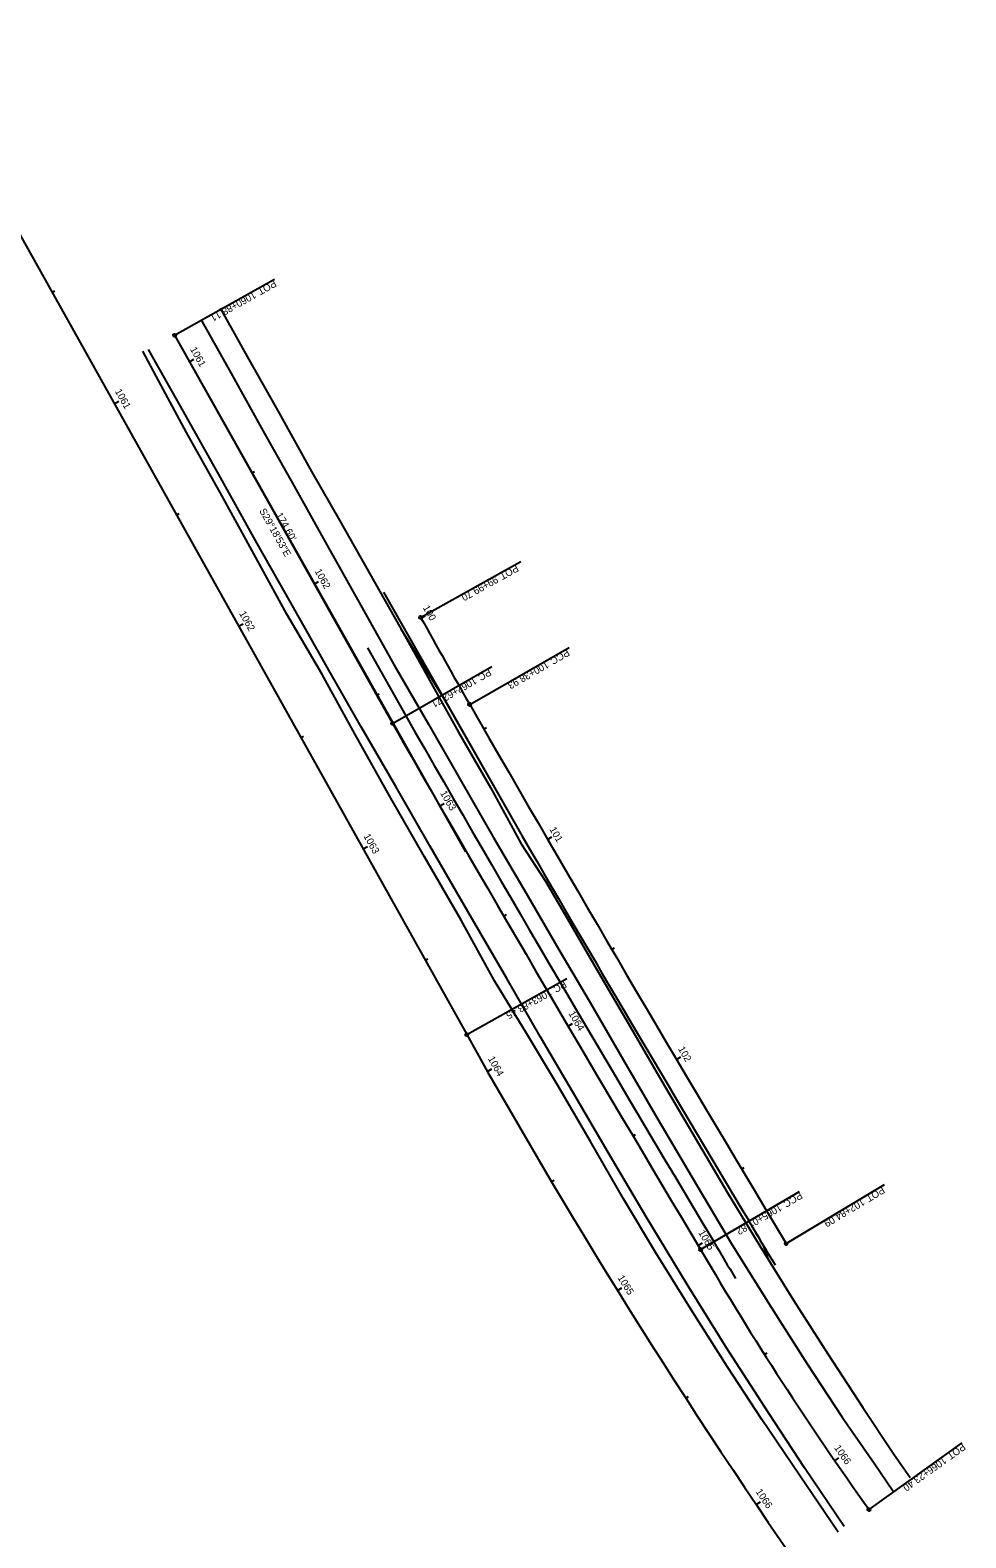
# Model space of a CAD drawing. Extents: x 1948127 to 1949841, y 151410 to 153356.
# Drawn here: x 1948495 to 1948862, y 152173 to 152764 of the extents above; entities that cross this region are included whole.
import ezdxf

# ---------------------------------------------------------------- set-up
doc = ezdxf.new("R2010")
doc.units = 0
for name, color, linetype in [('BR_P_Brg_Pad_Hidden', 7, 'Continuous'), ('BR_P_Gen_Hatch', 7, 'Continuous'), ('BR_P_Slab_Stl_Det', 7, 'Continuous'), ('BR_P_Slab_Stl_Det_Hidden', 7, 'Continuous'), ('BR_P_Sub_Deep_Centerline', 7, 'Continuous'), ('BR_P_Sub_Deep_Hidden', 7, 'Continuous'), ('CM_Corridor_Top_Mesh', 7, 'Continuous'), ('DR_P_Ditch', 7, 'Continuous'), ('DR_X_Storm_Sewer', 7, 'Continuous'), ('GE_X_Alignment_100_Stations', 7, 'Continuous'), ('MD_P_Surface_Chemically_Stabilized_Subgrade', 7, 'Continuous'), ('SC_Scratch1', 7, 'Continuous'), ('SC_Scratch11', 7, 'Continuous'), ('TX_P_1', 7, 'Continuous')]:
    doc.layers.add(name, color=color, linetype=linetype)

msp = doc.modelspace()

# ---------------------------------------------------------------- linework, layer by layer
at = {"layer": 'BR_P_Gen_Hatch'}
msp.add_line((1948551.61, 152644.81), (1948665.76, 152442.26), dxfattribs=at)
at = {"layer": 'BR_P_Slab_Stl_Det'}
for points in [[(1948562.39, 152650.4), (1948573.72, 152630.13), (1948586.43, 152607.26), (1948598.51, 152585.61), (1948611.32, 152562.7), (1948624.06, 152540.02), (1948637.72, 152515.73), (1948651.27, 152492.37), (1948663.63, 152470.62), (1948676.95, 152447.56), (1948689.61, 152426.05), (1948702.36, 152403.96), (1948714.65, 152383.15), (1948727.73, 152360.55), (1948741.26, 152337.36), (1948754.52, 152314.84), (1948770.02, 152288.76), (1948784.79, 152265.13), (1948799.87, 152241.41), (1948813.52, 152220.53), (1948826.05, 152202.51), (1948833.51, 152191.53)], [(1948814.36, 152177.61), (1948798.77, 152200.66), (1948784.61, 152222.18), (1948767.92, 152248.18), (1948752.79, 152272.55), (1948736.61, 152299.16), (1948721.69, 152324.29), (1948707.75, 152348.29), (1948695.05, 152369.83), (1948682, 152392.51), (1948666.63, 152418.86), (1948651.77, 152444.62), (1948638.4, 152467.86), (1948624.88, 152491.29), (1948612.64, 152512.63), (1948597.75, 152538.95), (1948584.01, 152563.11), (1948569.69, 152589.07), (1948555.07, 152614.97), (1948541.37, 152639.28)]]:
    msp.add_lwpolyline(points, dxfattribs=at)
at = {"layer": 'BR_P_Slab_Stl_Det_Hidden'}
for p, q in [((1948557.46, 152634.46), (1948559.2, 152635.44)), ((1948581.94, 152590.87), (1948582.98, 152591.45)), ((1948606.42, 152547.27), (1948608.16, 152548.25)), ((1948648.32, 152533.93), (1948650.07, 152534.9)), ((1948630.9, 152503.67), (1948631.95, 152504.26)), ((1948672.96, 152490.42), (1948674, 152491.02)), ((1948655.71, 152460.26), (1948657.44, 152461.26)), ((1948697.98, 152447.13), (1948699.71, 152448.13)), ((1948680.79, 152417.01), (1948681.83, 152417.61)), ((1948723.17, 152403.94), (1948724.21, 152404.55)), ((1948706.04, 152373.85), (1948707.77, 152374.87)), ((1948748.54, 152360.85), (1948750.26, 152361.87)), ((1948731.47, 152330.8), (1948732.5, 152331.41)), ((1948774.07, 152317.86), (1948775.1, 152318.48)), ((1948757.07, 152287.85), (1948758.79, 152288.88)), ((1948783.08, 152245.15), (1948784.09, 152245.79)), ((1948810.66, 152203.45), (1948812.31, 152204.59))]:
    msp.add_line(p, q, dxfattribs=at)
at = {"layer": 'BR_P_Sub_Deep_Centerline'}
for p, q in [((1948503.58, 152661.62), (1948504.63, 152662.21)), ((1948527.97, 152617.98), (1948529.72, 152618.95)), ((1948552.37, 152574.33), (1948553.42, 152574.92)), ((1948576.76, 152530.69), (1948578.51, 152531.67)), ((1948601.16, 152487.04), (1948602.21, 152487.63)), ((1948625.56, 152443.4), (1948627.3, 152444.38)), ((1948649.95, 152399.76), (1948651, 152400.34)), ((1948674.39, 152356.14), (1948676.13, 152357.12)), ((1948699.5, 152312.9), (1948700.53, 152313.51)), ((1948725.45, 152270.16), (1948727.14, 152271.21)), ((1948752.23, 152227.94), (1948753.23, 152228.59)), ((1948779.83, 152186.25), (1948781.49, 152187.37))]:
    msp.add_line(p, q, dxfattribs=at)
at = {"layer": 'BR_P_Sub_Deep_Hidden'}
msp.add_line((1948666.27, 152370.56), (1948705.55, 152392.51), dxfattribs=at)
msp.add_circle((1948666.27, 152370.56), 0.6, dxfattribs=at)
at = {"layer": 'CM_Corridor_Top_Mesh'}
for points in [[(1948562.39, 152650.4), (1948573.72, 152630.13), (1948586.43, 152607.26), (1948598.51, 152585.61), (1948611.32, 152562.7), (1948624.06, 152540.02), (1948637.72, 152515.73), (1948651.27, 152492.37), (1948663.63, 152470.62), (1948676.95, 152447.56), (1948689.61, 152426.05), (1948702.36, 152403.96), (1948714.65, 152383.15), (1948727.73, 152360.55), (1948741.26, 152337.36), (1948754.52, 152314.84), (1948770.02, 152288.76), (1948784.79, 152265.13), (1948799.87, 152241.41), (1948813.52, 152220.53), (1948826.05, 152202.51), (1948833.51, 152191.53)], [(1948814.36, 152177.61), (1948798.77, 152200.66), (1948784.61, 152222.18), (1948767.92, 152248.18), (1948752.79, 152272.55), (1948736.61, 152299.16), (1948721.69, 152324.29), (1948707.75, 152348.29), (1948695.05, 152369.83), (1948682, 152392.51), (1948666.63, 152418.86), (1948651.77, 152444.62), (1948638.4, 152467.86), (1948624.88, 152491.29), (1948612.64, 152512.63), (1948597.75, 152538.95), (1948584.01, 152563.11), (1948569.69, 152589.07), (1948555.07, 152614.97), (1948541.37, 152639.28)]]:
    msp.add_lwpolyline(points, dxfattribs=at)
at = {"layer": 'DR_P_Ditch'}
for p, q in [((1948633.62, 152544.11), (1948685.2, 152453.22)), ((1948640.35, 152529.74), (1948656.68, 152503.46)), ((1948656.68, 152503.46), (1948685.2, 152453.22)), ((1948656.68, 152503.46), (1948685.2, 152453.22)), ((1948776.88, 152297.6), (1948776.94, 152297.49)), ((1948776.88, 152297.6), (1948776.94, 152297.49)), ((1948776.88, 152297.6), (1948776.94, 152297.49)), ((1948776.94, 152297.49), (1948777, 152297.39)), ((1948776.94, 152297.49), (1948777, 152297.39)), ((1948776.94, 152297.49), (1948777, 152297.39)), ((1948782.53, 152288.02), (1948784.44, 152282.6))]:
    msp.add_line(p, q, dxfattribs=at)
for centre, radius, start, end in [((1959364.39, 158640.02), 12341.86, 210.085088, 210.92362), ((1959364.39, 158640.02), 12341.86, 210.085088, 210.92362), ((1959364.39, 158640.02), 12341.86, 210.085088, 210.92362), ((1949896.82, 152951.97), 1297.1, 210.30805, 211.19069), ((1949896.82, 152951.97), 1297.1, 210.30805, 210.78706), ((1949896.82, 152951.97), 1297.1, 210.30805, 210.78706)]:
    msp.add_arc(centre, radius, start, end, dxfattribs=at)
at = {"layer": 'DR_X_Storm_Sewer'}
for p, q in [((1948551.64, 152644.83), (1948590.87, 152666.86)), ((1948648.18, 152534.19), (1948687.49, 152556.08)), ((1948667.44, 152500.02), (1948706.46, 152522.43)), ((1948637.12, 152492.59), (1948676.17, 152514.96)), ((1948791.58, 152288.61), (1948830.16, 152311.76)), ((1948758.01, 152286.29), (1948796.86, 152309)), ((1948824.11, 152184.3), (1948860.7, 152210.49))]:
    msp.add_line(p, q, dxfattribs=at)
for centre in [(1948551.64, 152644.83), (1948648.18, 152534.19), (1948667.44, 152500.02), (1948637.12, 152492.59), (1948758.01, 152286.29), (1948791.58, 152288.61), (1948824.11, 152184.3)]:
    msp.add_circle(centre, 0.6, dxfattribs=at)
at = {"layer": 'GE_X_Alignment_100_Stations'}
for points in [[(1948569.54, 152655.45), (1948580.78, 152635.37), (1948592.65, 152614.23), (1948605.3, 152591.41), (1948616.41, 152572.05), (1948628.19, 152551.33), (1948639.95, 152530.43), (1948651.66, 152509.56), (1948663.01, 152489.14), (1948675.59, 152467.47), (1948687.61, 152445.42), (1948697.12, 152430.76), (1948705.79, 152416), (1948717.95, 152394.92), (1948730.53, 152373.49), (1948742.79, 152352.28), (1948755.91, 152330.05), (1948768.46, 152308.76), (1948781.28, 152287.71), (1948794.43, 152266.42), (1948807.98, 152245.32), (1948821.66, 152224.39), (1948833.86, 152206.01), (1948840.23, 152196.92)], [(1948811.98, 152175.48), (1948796.79, 152197.82), (1948782.08, 152219.62), (1948768.47, 152240.47), (1948754.77, 152261.87), (1948740.51, 152284.98), (1948727.79, 152306.21), (1948714.8, 152328.59), (1948701.97, 152350.65), (1948689.83, 152370.86), (1948677.11, 152391.66), (1948664.12, 152415.47), (1948649.69, 152440.32), (1948635.96, 152464.27), (1948622.5, 152488.21), (1948609.36, 152512.09), (1948595.71, 152535.44), (1948582.67, 152559.08), (1948570.16, 152582.02), (1948556.36, 152606.71), (1948544.38, 152628.8), (1948539.13, 152638.61)]]:
    msp.add_lwpolyline(points, dxfattribs=at)
at = {"layer": 'MD_P_Surface_Chemically_Stabilized_Subgrade'}
for p, q in [((1948627.32, 152522.3), (1948642.34, 152495.55)), ((1948776.88, 152297.6), (1948776.94, 152297.49)), ((1948776.94, 152297.49), (1948777, 152297.39)), ((1948763.16, 152289.37), (1948763.17, 152289.35)), ((1948763.17, 152289.35), (1948763.19, 152289.32))]:
    msp.add_line(p, q, dxfattribs=at)
for centre, radius, start, end in [((1959364.39, 158640.02), 12357.86, 209.815678, 210.92362), ((1959364.39, 158640.02), 12341.86, 210.085088, 210.92362), ((1949896.82, 152951.97), 1297.1, 210.30805, 211.19069), ((1949896.82, 152951.97), 1313.1, 210.30805, 211.03682)]:
    msp.add_arc(centre, radius, start, end, dxfattribs=at)
at = {"layer": 'SC_Scratch1'}
msp.add_line((1948127.85, 153333.82), (1948666.27, 152370.56), dxfattribs=at)
msp.add_arc((1950889.32, 153613.15), 2546.76, 209.20338, 215.20324, dxfattribs=at)
at = {"layer": 'TX_P_1'}
msp.add_line((1948551.64, 152644.83), (1948637.12, 152492.59), dxfattribs=at)
for centre, radius, start, end in [((1952154.81, 154486.98), 4013.71, 209.11277, 209.67273), ((1959736.57, 158857.55), 12764.95, 209.870826, 210.97126), ((1959364.39, 158640.02), 12363.86, 209.815556, 210.92362), ((1949896.82, 152951.97), 1319.1, 210.30805, 215.58877)]:
    msp.add_arc(centre, radius, start, end, dxfattribs=at)

# ---------------------------------------------------------------- texts
at = {"layer": 'BR_P_Brg_Pad_Hidden'}
msp.add_text('S29°18\'53"E', height=2.8, rotation=299.31461, dxfattribs=at).set_placement((1948584.77, 152576.01))
at = {"layer": 'BR_P_Slab_Stl_Det_Hidden'}
for s, rotation, p in [('1061', 299.31461, (1948557.62, 152639.37)), ('1062', 299.31461, (1948606.5, 152552.32)), ('100', 299.11702, (1948648.95, 152538.03)), ('1063', 299.98835, (1948655.74, 152465.3)), ('101', 300.14495, (1948698.62, 152451.1)), ('1064', 300.45176, (1948706.05, 152378.87)), ('102', 300.5938, (1948749.06, 152364.97)), ('1065', 300.91518, (1948757.01, 152292.92)), ('1066', 304.57246, (1948810.28, 152208.5))]:
    msp.add_text(s, height=2.8, rotation=rotation, dxfattribs=at).set_placement(p)
at = {"layer": 'BR_P_Sub_Deep_Centerline'}
for s, rotation, p in [('1061', 299.20338, (1948528.15, 152622.89)), ('1062', 299.20338, (1948576.86, 152535.74)), ('1063', 299.20338, (1948625.66, 152448.44)), ('1064', 299.57571, (1948674.47, 152361.16)), ('1065', 301.82546, (1948725.3, 152275.22)), ('1066', 304.07522, (1948779.49, 152191.3))]:
    msp.add_text(s, height=2.8, rotation=rotation, dxfattribs=at).set_placement(p)
at = {"layer": 'BR_P_Sub_Deep_Hidden'}
for s, p in [('1063+83.45', (1948698.73, 152388.64)), ('PC', (1948704.42, 152391.83))]:
    msp.add_text(s, height=2.8, rotation=209.20338, dxfattribs=at).set_placement(p)
at = {"layer": 'DR_X_Storm_Sewer'}
for s, rotation, p in [('POT', 209.31461, (1948590.59, 152666.65)), ('1060+88.11', 209.31461, (1948582.63, 152662.18)), ('POT', 209.11277, (1948685.59, 152554.97)), ('99+99.70', 209.11277, (1948677.61, 152550.53)), ('100+38.93', 209.87083, (1948697.49, 152517.22)), ('PCC', 209.87083, (1948705.59, 152521.88)), ('1062+62.71', 209.81556, (1948669.22, 152510.93)), ('PC', 209.81556, (1948674.88, 152514.17)), ('POT', 210.97126, (1948829.2, 152311.13)), ('1065+01.82', 210.30805, (1948788.87, 152304.28)), ('PCC', 210.30805, (1948796.94, 152308.99)), ('102+84.09', 210.97126, (1948821.37, 152306.43)), ('POT', 215.58877, (1948860.7, 152210.43)), ('1066+23.40', 215.58877, (1948853.28, 152205.12))]:
    msp.add_text(s, height=2.8, rotation=rotation, dxfattribs=at).set_placement(p)
at = {"layer": 'SC_Scratch11'}
msp.add_text("174.60'", height=2.8, rotation=299.31461, dxfattribs=at).set_placement((1948591.25, 152574.39))

doc.saveas('drawing.dxf')
